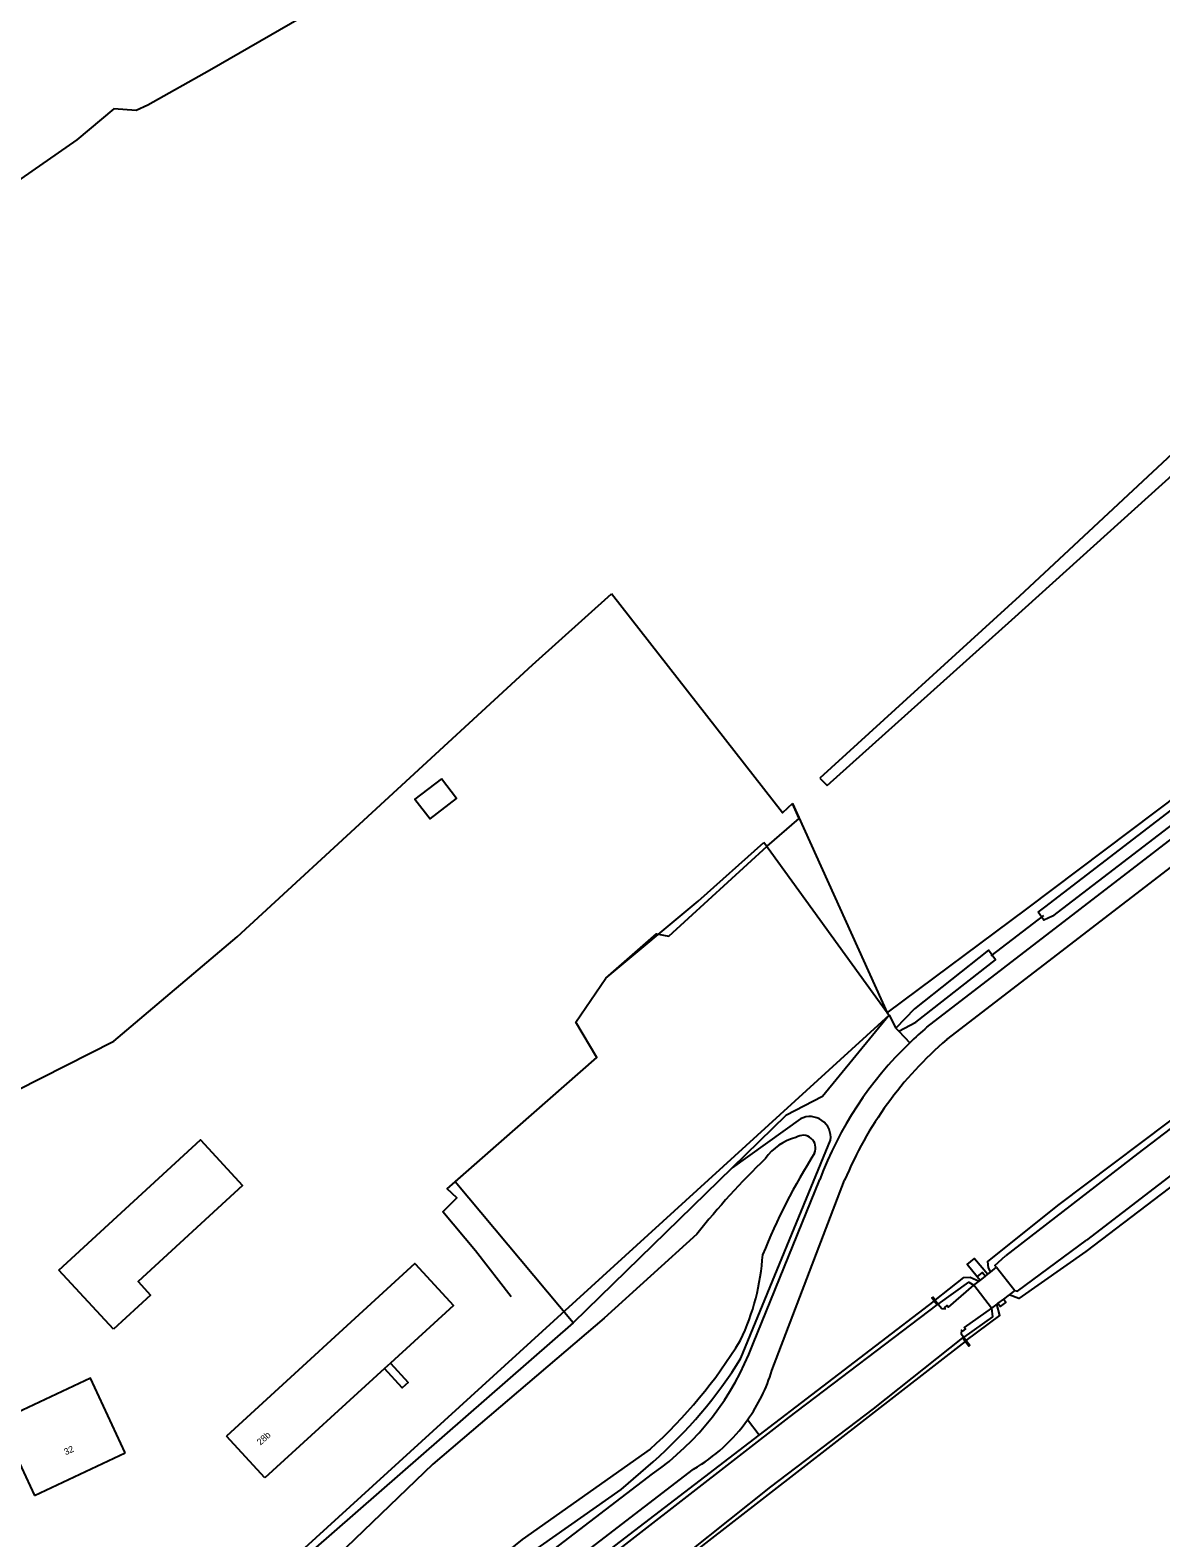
# Model space of a CAD drawing. Extents: x 134297 to 137000, y 403500 to 406000.
# Drawn here: x 136245.2 to 136417.4, y 404556.9 to 404786.5 of the extents above; entities that cross this region are included whole.
import ezdxf

# ---------------------------------------------------------------- set-up
doc = ezdxf.new("R2010")
doc.units = 0
for name, color, linetype in [('gg-afsc-draadraster', 7, 'Continuous'), ('gg-afsc-lijn draadraster', 7, 'Continuous'), ('gg-anno-huisnummerreeks BGT', 7, 'Continuous'), ('gg-bbg-bijgebouw', 7, 'Continuous'), ('gg-bbg-gedigitaliseerde bebouwing', 7, 'Continuous'), ('gg-bbg-gedigitaliseerde bijgebouw', 7, 'Continuous'), ('gg-bbg-hoofdgebouw', 7, 'Continuous'), ('gg-bbg-luifel en loopbrug', 7, 'Continuous'), ('gg-knt-bronhoudergrens', 7, 'Continuous'), ('gg-knt-verharding', 7, 'Continuous'), ('gg-kntw-bovenkant insteek waterloop', 7, 'Continuous'), ('gg-kntw-waterlijn', 7, 'Continuous'), ('gg-kwrk-duiker nz buis', 7, 'Continuous'), ('gg-kwrk-lijn stuw', 7, 'Continuous'), ('gg-kwrk-stuw', 7, 'Continuous'), ('gt-grn-vlakafsluiter', 7, 'Continuous')]:
    doc.layers.add(name, color=color, linetype=linetype)

msp = doc.modelspace()

# ---------------------------------------------------------------- linework, layer by layer
at = {"layer": 'gg-afsc-draadraster'}
msp.add_line((136365.44, 404672.56), (136366.55, 404671.43), dxfattribs=at)
for points in [[(136490.49, 404825.08), (136488.39, 404825.82), (136475.92, 404802.22), (136457.51, 404769.04), (136448.46, 404752.09), (136445.48, 404747.83), (136433.38, 404735.25), (136395.84, 404700.3), (136365.44, 404672.56)], [(136375.68, 404636.86), (136396.99, 404652.69), (136448.01, 404691.08), (136541.44, 404761.58), (136583.58, 404793.52), (136622.1, 404822.52)], [(136366.55, 404671.43), (136394.67, 404696.68), (136421.76, 404721.07)], [(136361.26, 404668.71), (136359.75, 404667.28), (136333.71, 404700.64)]]:
    msp.add_lwpolyline(points, dxfattribs=at)
at = {"layer": 'gg-afsc-lijn draadraster'}
for p, q in [((136365.44, 404672.56), (136366.55, 404671.43)), ((136361.26, 404668.71), (136375.68, 404636.86)), ((136375.68, 404636.86), (136356.92, 404662.79)), ((136375.98, 404636.47), (136249.06, 404520.82))]:
    msp.add_line(p, q, dxfattribs=at)
for points in [[(136490.49, 404825.08), (136488.39, 404825.82), (136475.92, 404802.22), (136457.51, 404769.04), (136448.46, 404752.09), (136445.48, 404747.83), (136433.38, 404735.25), (136395.84, 404700.3), (136365.44, 404672.56)], [(136375.68, 404636.86), (136396.99, 404652.69), (136448.01, 404691.08), (136541.44, 404761.58), (136583.58, 404793.52), (136622.1, 404822.52)], [(136366.55, 404671.43), (136394.67, 404696.68), (136421.76, 404721.07)], [(136361.26, 404668.71), (136359.75, 404667.28), (136333.71, 404700.64)], [(136318.46, 404593.58), (136312.99, 404600.62), (136308.02, 404606.51), (136310.16, 404608.66), (136308.7, 404610.02), (136331.49, 404630.05), (136328.3, 404635.4), (136332.83, 404642.1), (136346.94, 404653.83), (136356.92, 404662.79)]]:
    msp.add_lwpolyline(points, dxfattribs=at)
at = {"layer": 'gg-bbg-bijgebouw'}
msp.add_line((136257.86, 404588.67), (136249.54, 404597.63), dxfattribs=at)
at = {"layer": 'gg-bbg-gedigitaliseerde bebouwing'}
for p, q in [((136299.15, 404582.68), (136280.9, 404566.03)), ((136300.04, 404583.49), (136299.15, 404582.68))]:
    msp.add_line(p, q, dxfattribs=at)
for points in [[(136303.82, 404598.63), (136303.79, 404598.66), (136275.07, 404572.4)], [(136303.82, 404598.63), (136309.64, 404592.25), (136300.04, 404583.49)], [(136259.67, 404569.83), (136254.36, 404581.19), (136240.52, 404574.71), (136245.83, 404563.35)]]:
    msp.add_lwpolyline(points, dxfattribs=at)
at = {"layer": 'gg-bbg-gedigitaliseerde bijgebouw'}
for points in [[(136307.81, 404672.45), (136303.79, 404669.36), (136306.09, 404666.37), (136310.11, 404669.45), (136307.81, 404672.45)], [(136249.54, 404597.63), (136271.13, 404617.48), (136277.51, 404610.54), (136261.61, 404595.93), (136263.51, 404593.86), (136257.86, 404588.67)]]:
    msp.add_lwpolyline(points, dxfattribs=at)
at = {"layer": 'gg-bbg-hoofdgebouw'}
for p, q in [((136280.9, 404566.03), (136275.07, 404572.4)), ((136245.83, 404563.35), (136259.67, 404569.83))]:
    msp.add_line(p, q, dxfattribs=at)
at = {"layer": 'gg-bbg-luifel en loopbrug'}
msp.add_lwpolyline([(136300.04, 404583.49), (136302.73, 404580.53), (136301.85, 404579.73), (136299.15, 404582.68)], dxfattribs=at)
at = {"layer": 'gg-knt-bronhoudergrens'}
for p, q in [((136375.98, 404636.47), (136377.04, 404634.48)), ((136377.45, 404634.02), (136379.13, 404632.26)), ((136352.09, 404613.22), (136327.86, 404589.62)), ((136327.86, 404589.62), (136288.26, 404555.05)), ((136356.21, 404572.55), (136354.44, 404574.87))]:
    msp.add_line(p, q, dxfattribs=at)
for points in [[(136317.98, 404877.07), (136319.47, 404878.08), (136322.79, 404873.18), (136330.65, 404863.19), (136313.19, 404850.76), (136274.43, 404824.83), (136294.8, 404795.99), (136287.84, 404789.14), (136272.48, 404780.34), (136263.09, 404775.03), (136261.31, 404774.23), (136257.93, 404774.49), (136252.31, 404769.75), (136242.58, 404763.02), (136211.65, 404741.71), (136193.52, 404730.34), (136186.61, 404725.94), (136191.19, 404717.73)], [(136204.08, 404605.28), (136217.5, 404612.06), (136215.37, 404616.22), (136218.96, 404617.97), (136221.24, 404613.95), (136257.95, 404632.5), (136276.71, 404648.41), (136321.69, 404689.82), (136333.71, 404700.64)], [(136327.86, 404589.62), (136309.93, 404611.11), (136331.49, 404630.05), (136328.3, 404635.4), (136332.83, 404642.1), (136340.59, 404648.85), (136342.47, 404648.49), (136357.42, 404662.21), (136362.31, 404666.41), (136361.26, 404668.71)], [(136375.98, 404636.47), (136365.85, 404624.11), (136360.28, 404621.19), (136352.09, 404613.22)]]:
    msp.add_lwpolyline(points, dxfattribs=at)
at = {"layer": 'gg-knt-verharding'}
for p, q in [((136355.23, 404586.31), (136365.43, 404611.45)), ((136358.15, 404582.38), (136369.22, 404611.35)), ((136389.84, 404596.1), (136389.42, 404596.66))]:
    msp.add_line(p, q, dxfattribs=at)
for points in [[(136381.76, 404634.63), (136451.12, 404688.05), (136543.95, 404758.39), (136626.52, 404820.32), (136665.44, 404848.88)], [(136384.78, 404632.77), (136453.77, 404685.84), (136545.65, 404755.6), (136587.95, 404787.62), (136629.23, 404818.77), (136666.02, 404845.47)], [(136389.42, 404596.66), (136389.39, 404596.64), (136387.88, 404598.5), (136389, 404599.42), (136391.01, 404597.03)], [(136389.42, 404596.66), (136390.22, 404597.29), (136390.65, 404596.74)], [(136392.55, 404592.61), (136392.98, 404592.12), (136393.78, 404592.71), (136393.39, 404593.24)], [(136253.28, 404499.83), (136256.84, 404503), (136339.95, 404566.62)], [(136254.28, 404496.72), (136258.65, 404500.03), (136346.21, 404567.34)]]:
    msp.add_lwpolyline(points, dxfattribs=at)
for centre, radius, start, end in [((136418.06, 404591.72), 56.21, 130.2284, 133.8327), ((136418.08, 404591.69), 56.24, 133.8299, 159.4315), ((136421.76, 404589.55), 56.88, 130.5533, 157.467), ((136315.85, 404601.08), 42.05, 304.9613, 339.4408), ((136332.86, 404590.19), 26.47, 324.6285, 342.8349), ((136332.86, 404590.2), 26.47, 300.2977, 324.6235)]:
    msp.add_arc(centre, radius, start, end, dxfattribs=at)
at = {"layer": 'gg-kntw-bovenkant insteek waterloop'}
for p, q in [((136472.76, 404661.13), (136401.83, 404607.65)), ((136379.84, 404637.45), (136377.04, 404634.48)), ((136377.04, 404634.48), (136377.45, 404634.02)), ((136362.5, 404620.7), (136352.09, 404613.22)), ((136353.43, 404584.27), (136367.07, 404617.44)), ((136356.21, 404572.55), (136382.85, 404592.94)), ((136387.58, 404586.8), (136275.79, 404500)), ((136265.35, 404502.98), (136356.21, 404572.55))]:
    msp.add_line(p, q, dxfattribs=at)
for points in [[(136398.68, 404652.17), (136399.71, 404652.91), (136448.68, 404690.55), (136541.52, 404761.15), (136583.62, 404792.87), (136615.77, 404817.08), (136617.32, 404815.32), (136585.59, 404790.59), (136543.89, 404759.49), (136450, 404689.19), (136400.86, 404651.54), (136399.56, 404650.94), (136398.68, 404652.17)], [(136645.35, 404782.68), (136405.94, 404600.51), (136395.73, 404593.35), (136394.26, 404593.91)], [(136377.45, 404634.02), (136380.06, 404635.4), (136392.18, 404644.93), (136391.13, 404646.38), (136379.84, 404637.45)], [(136401.83, 404607.65), (136390.99, 404598.98), (136391.06, 404598.03), (136391.43, 404597.36)], [(136383.03, 404593.09), (136387.37, 404596.53), (136388.33, 404596.6), (136389.69, 404595.99)], [(136387.75, 404586.93), (136392.85, 404590.76), (136392.4, 404592.48)], [(136263.32, 404510.03), (136287.06, 404527.86), (136313.23, 404547.78), (136319.15, 404552.98), (136335.21, 404564.25), (136340.07, 404568.49)]]:
    msp.add_lwpolyline(points, dxfattribs=at)
for centre, radius, start, end in [((136363.93, 404617.87), 3.17, 352.2662, 116.7178), ((136293.62, 404621.38), 70.39, 311.2897, 328.1833)]:
    msp.add_arc(centre, radius, start, end, dxfattribs=at)
at = {"layer": 'gg-kntw-waterlijn'}
for p, q in [((136383.3, 404592.36), (136383.48, 404592.49)), ((136387.35, 404587.47), (136387.16, 404587.34))]:
    msp.add_line(p, q, dxfattribs=at)
for points in [[(136705.26, 404842.95), (136704.05, 404841.49), (136696.9, 404833.84), (136686.55, 404824.66), (136636.89, 404786.92), (136608.34, 404765.49), (136565.56, 404731.85), (136509.64, 404688.6), (136495.78, 404678.11), (136480.58, 404666.21), (136462.34, 404652.19), (136445.93, 404639.88), (136413.86, 404615.42), (136393.71, 404599.81)], [(136709.42, 404839), (136704.61, 404833.57), (136692.6, 404822.08), (136608.69, 404756.42), (136539.82, 404704.98), (136406.07, 404602.23)], [(136346.72, 404603.14), (136332.59, 404590.36), (136306.49, 404568.12), (136291.98, 404554.17), (136274.45, 404537.3), (136257.11, 404522.41)], [(136395.13, 404594.58), (136395.54, 404594.45), (136406.07, 404602.23)], [(136392.37, 404598.09), (136392.11, 404598.38), (136393.71, 404599.81)], [(136383.48, 404592.49), (136388.11, 404595.85), (136388.92, 404595.38)], [(136257.03, 404490.79), (136256.71, 404491.55), (136256.26, 404493.17), (136260.63, 404497.14), (136298.77, 404527.09), (136360.74, 404575.2), (136383.3, 404592.36)], [(136391.59, 404591.87), (136391.72, 404590.54), (136387.35, 404587.47)], [(136387.16, 404587.34), (136373.57, 404576.53), (136357.92, 404564.68), (136345.44, 404554.7), (136337.49, 404548.92), (136327.12, 404540.76), (136314.28, 404530.94), (136295.96, 404516.53), (136277.19, 404502.18), (136262.97, 404490.8), (136259.25, 404488.43), (136257.8, 404488.96), (136257.49, 404489.69)], [(136339.59, 404570.4), (136320.1, 404556.66), (136296.14, 404537.27), (136275.21, 404521.72), (136262.17, 404512.24)]]:
    msp.add_lwpolyline(points, dxfattribs=at)
for centre, radius, start, end in [((136362.87, 404616.26), 1.93, 335.4309, 123.2861), ((136363.85, 404609.97), 8.16, 104.4795, 145.1117), ((136438.39, 404530.41), 117.02, 133.9639, 141.5706), ((136449.17, 404562.52), 99.75, 147.9497, 157.9277), ((136321.36, 404602.22), 35.45, 334.54, 356.4185), ((136289.34, 404626.14), 75.05, 312.0361, 328.5475)]:
    msp.add_arc(centre, radius, start, end, dxfattribs=at)
at = {"layer": 'gg-kwrk-duiker nz buis'}
msp.add_line((136391.55, 404645.51), (136399.55, 404651.66), dxfattribs=at)
at = {"layer": 'gg-kwrk-lijn stuw'}
msp.add_line((136392.37, 404598.09), (136395.13, 404594.58), dxfattribs=at)
at = {"layer": 'gg-kwrk-stuw'}
for p, q in [((136391.43, 404597.36), (136392.37, 404598.09)), ((136392.37, 404598.09), (136395.13, 404594.58)), ((136388.92, 404595.38), (136389.69, 404595.99)), ((136391.59, 404591.87), (136388.92, 404595.38)), ((136389.69, 404595.99), (136389.84, 404596.1)), ((136389.84, 404596.1), (136390.65, 404596.74)), ((136390.65, 404596.74), (136391.01, 404597.03)), ((136391.01, 404597.03), (136391.43, 404597.36)), ((136383.3, 404592.36), (136382.85, 404592.94)), ((136383.03, 404593.09), (136383.48, 404592.49)), ((136393.39, 404593.24), (136392.55, 404592.61)), ((136394.26, 404593.91), (136393.39, 404593.24)), ((136395.13, 404594.58), (136394.26, 404593.91)), ((136392.4, 404592.48), (136391.59, 404591.87)), ((136392.55, 404592.61), (136392.4, 404592.48)), ((136387.58, 404586.8), (136387.16, 404587.34)), ((136387.35, 404587.47), (136387.75, 404586.93))]:
    msp.add_line(p, q, dxfattribs=at)
for points in [[(136383.48, 404592.49), (136384.01, 404591.8), (136384.54, 404591.74), (136384.43, 404591.94), (136384.85, 404592.28), (136385.04, 404592.04), (136388.92, 404595.38)], [(136382.85, 404592.94), (136382.48, 404593.42), (136382.68, 404593.55), (136383.03, 404593.09)], [(136391.59, 404591.87), (136387.44, 404588.93), (136387.62, 404588.7), (136387.15, 404588.34), (136387, 404588.52), (136386.97, 404587.98), (136387.35, 404587.47)], [(136387.75, 404586.93), (136388.3, 404586.21), (136388.13, 404586.08), (136387.58, 404586.8)]]:
    msp.add_lwpolyline(points, dxfattribs=at)
at = {"layer": 'gt-grn-vlakafsluiter'}
msp.add_line((136375.68, 404636.86), (136375.98, 404636.47), dxfattribs=at)

# ---------------------------------------------------------------- texts
at = {"layer": 'gg-anno-huisnummerreeks BGT'}
for s, rotation, p in [('28b', 42.4, (136280.26, 404570.93)), ('32', 25.1, (136250.61, 404569.45))]:
    msp.add_text(s, height=1, rotation=rotation, dxfattribs=at).set_placement(p)

doc.saveas('drawing.dxf')
